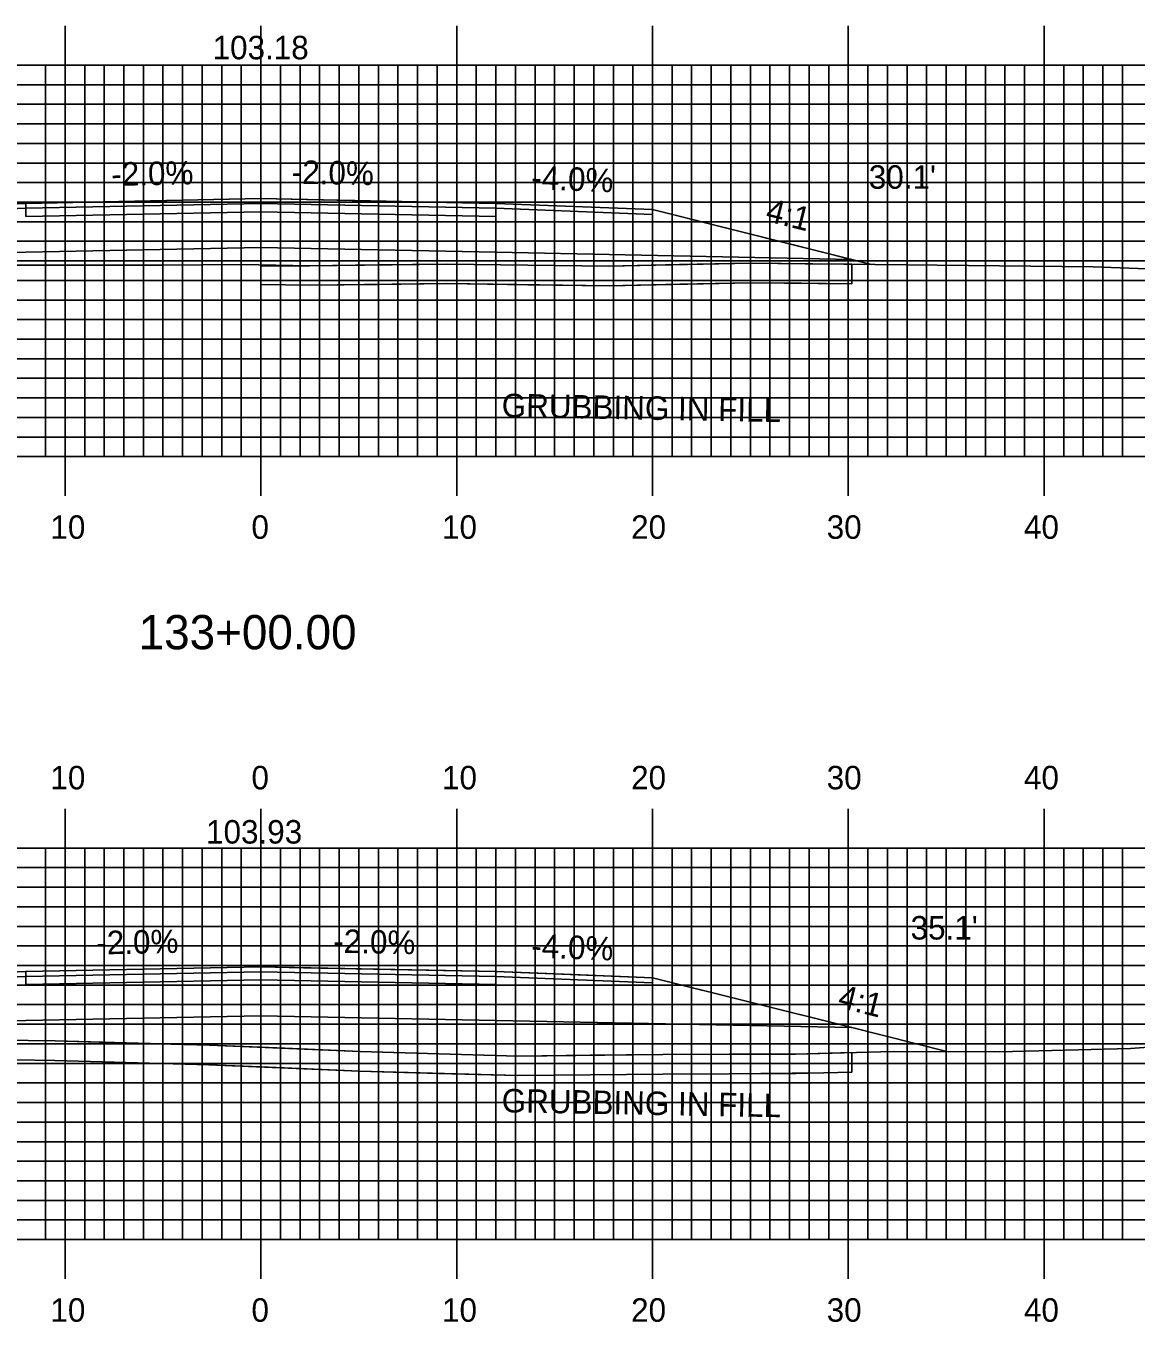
# Model space of a CAD drawing. Extents: x 1774383 to 1774727, y 442591 to 442811.
# Drawn here: x 1774537.2 to 1774593.9, y 442689.4 to 442755.7 of the extents above; entities that cross this region are included whole.
import ezdxf

# ---------------------------------------------------------------- set-up
doc = ezdxf.new("R2010")
doc.units = 0
for name, color, linetype in [('ANNOTATION', 7, 'Continuous'), ('D_Roadway_Centerline', 7, 'Continuous'), ('D_Roadway_Centerline_Text', 7, 'Continuous'), ('D_Roadway_Edge_Shoulder', 7, 'Continuous'), ('D_Roadway_Edge_TW', 7, 'Continuous'), ('D_Roadway_Pavement', 7, 'Continuous'), ('D_Roadway_SlopeLines', 7, 'Continuous'), ('D_Roadway_SubGrade', 7, 'Continuous'), ('D_Text_Standard', 7, 'Continuous'), ('GRUBBING IN FILL', 7, 'Continuous'), ('H_V ANNOTATION', 7, 'Continuous'), ('MAJOR', 7, 'Continuous'), ('MINOR', 7, 'Continuous'), ('S_Roadway_Centerline', 7, 'Continuous')]:
    doc.layers.add(name, color=color, linetype=linetype)

msp = doc.modelspace()

# ---------------------------------------------------------------- linework, layer by layer
at = {"layer": 'D_Roadway_Centerline'}
for points in [[(1774517.069, 442743.258), (1774518.981, 442743.736), (1774518.998, 442743.74), (1774519.832, 442743.949), (1774529.172, 442746.284), (1774537.172, 442746.604), (1774538.705, 442746.635), (1774549.172, 442746.844), (1774556.935, 442746.689), (1774561.172, 442746.604), (1774569.172, 442746.284), (1774579.347, 442743.74), (1774580.365, 442743.486)], [(1774514.75, 442703.428), (1774517.172, 442704.034), (1774518.998, 442704.49), (1774521.759, 442705.181), (1774529.172, 442707.034), (1774537.172, 442707.354), (1774537.174, 442707.354), (1774549.172, 442707.594), (1774551.354, 442707.551), (1774561.173, 442707.354), (1774565.061, 442707.199), (1774569.172, 442707.034), (1774573.892, 442705.854), (1774579.346, 442704.49), (1774584.264, 442703.261)]]:
    msp.add_lwpolyline(points, dxfattribs=at)
at = {"layer": 'D_Roadway_Edge_Shoulder'}
for points in [[(1774537.172, 442746.604), (1774529.172, 442746.284), (1774529.172, 442746.034), (1774537.172, 442746.354)], [(1774561.172, 442746.604), (1774569.172, 442746.284), (1774569.172, 442746.034), (1774561.172, 442746.354)], [(1774537.172, 442707.354), (1774529.172, 442707.034), (1774529.172, 442706.784), (1774537.172, 442707.104)], [(1774561.172, 442707.354), (1774569.172, 442707.034), (1774569.172, 442706.784), (1774561.172, 442707.104)]]:
    msp.add_lwpolyline(points, close=True, dxfattribs=at)
at = {"layer": 'D_Roadway_Edge_TW'}
for points in [[(1774537.172, 442746.354), (1774537.172, 442746.604), (1774549.172, 442746.844), (1774561.172, 442746.604), (1774561.172, 442746.354), (1774549.172, 442746.594)], [(1774537.172, 442707.104), (1774537.172, 442707.354), (1774549.172, 442707.594), (1774561.172, 442707.354), (1774561.172, 442707.104), (1774549.172, 442707.344)]]:
    msp.add_lwpolyline(points, close=True, dxfattribs=at)
at = {"layer": 'D_Roadway_Pavement'}
for points in [[(1774537.172, 442745.937), (1774537.172, 442746.354), (1774549.172, 442746.594), (1774561.172, 442746.354), (1774561.172, 442745.937), (1774549.172, 442746.177)], [(1774537.172, 442706.687), (1774537.172, 442707.104), (1774549.172, 442707.344), (1774561.172, 442707.104), (1774561.172, 442706.687), (1774549.172, 442706.927)]]:
    msp.add_lwpolyline(points, close=True, dxfattribs=at)
at = {"layer": 'D_Roadway_SlopeLines'}
for points in [[(1774569.172, 442746.284), (1774580.365, 442743.485)], [(1774569.172, 442707.034), (1774579.346, 442704.49), (1774584.264, 442703.261)]]:
    msp.add_lwpolyline(points, dxfattribs=at)
at = {"layer": 'D_Roadway_SubGrade'}
for points in [[(1774537.172, 442744.104), (1774518.998, 442743.74), (1774529.172, 442746.284), (1774529.172, 442746.034), (1774537.172, 442746.354), (1774549.172, 442746.594), (1774561.172, 442746.354), (1774569.172, 442746.034), (1774569.172, 442746.284), (1774579.347, 442743.74), (1774561.172, 442744.104), (1774549.172, 442744.344)], [(1774537.172, 442704.854), (1774518.998, 442704.49), (1774529.172, 442707.034), (1774529.172, 442706.784), (1774537.172, 442707.104), (1774549.172, 442707.344), (1774561.172, 442707.104), (1774569.172, 442706.784), (1774569.172, 442707.034), (1774579.346, 442704.49), (1774561.172, 442704.854), (1774549.172, 442705.094)]]:
    msp.add_lwpolyline(points, close=True, dxfattribs=at)
at = {"layer": 'GRUBBING IN FILL'}
for p, q in [((1774549.172, 442742.459), (1774549.172, 442743.416)), ((1774549.172, 442743.416), (1774551.667, 442743.416)), ((1774549.172, 442742.459), (1774549.172, 442743.416)), ((1774549.172, 442743.416), (1774551.667, 442743.416)), ((1774579.347, 442743.496), (1774579.347, 442742.496)), ((1774579.347, 442743.496), (1774579.347, 442742.496)), ((1774579.346, 442703.217), (1774579.346, 442702.216)), ((1774579.346, 442703.217), (1774579.346, 442702.216))]:
    msp.add_line(p, q, dxfattribs=at)
for points in [[(1774549.172, 442742.459), (1774549.172, 442743.416), (1774551.667, 442743.416), (1774555.169, 442743.46), (1774558.671, 442743.503), (1774562.81, 442743.449), (1774566.948, 442743.394), (1774570.557, 442743.473), (1774574.166, 442743.552), (1774576.961, 442743.522), (1774579.347, 442743.496), (1774579.347, 442742.496), (1774576.759, 442742.524), (1774574.172, 442742.552), (1774570.562, 442742.473), (1774566.953, 442742.394), (1774562.812, 442742.449), (1774558.671, 442742.503), (1774555.168, 442742.46), (1774551.665, 442742.416)], [(1774549.172, 442742.459), (1774549.172, 442743.416), (1774551.667, 442743.416), (1774555.169, 442743.46), (1774558.671, 442743.503), (1774562.81, 442743.449), (1774566.948, 442743.394), (1774570.557, 442743.473), (1774574.166, 442743.552), (1774576.961, 442743.522), (1774579.347, 442743.496), (1774579.347, 442742.496), (1774576.759, 442742.524), (1774574.172, 442742.552), (1774570.562, 442742.473), (1774566.953, 442742.394), (1774562.812, 442742.449), (1774558.671, 442742.503), (1774555.168, 442742.46), (1774551.665, 442742.416)], [(1774518.998, 442702.527), (1774525.033, 442702.668), (1774531.069, 442702.808), (1774534.516, 442702.875), (1774538.645, 442702.811), (1774546.521, 442702.599), (1774549.172, 442702.486), (1774549.172, 442703.487), (1774546.555, 442703.599), (1774542.611, 442703.705), (1774538.666, 442703.811), (1774534.514, 442703.875), (1774532.781, 442703.841), (1774531.048, 442703.808), (1774522.901, 442703.618), (1774518.998, 442703.527)], [(1774518.998, 442702.527), (1774525.033, 442702.668), (1774531.069, 442702.808), (1774534.516, 442702.875), (1774538.645, 442702.811), (1774546.521, 442702.599), (1774549.172, 442702.486), (1774549.172, 442703.487), (1774546.555, 442703.599), (1774542.611, 442703.705), (1774538.666, 442703.811), (1774534.514, 442703.875), (1774532.781, 442703.841), (1774531.048, 442703.808), (1774522.901, 442703.618), (1774518.998, 442703.527)], [(1774549.172, 442703.487), (1774550.401, 442703.435), (1774554.247, 442703.271), (1774558.268, 442703.156), (1774562.289, 442703.041), (1774565.991, 442703.08), (1774569.692, 442703.12), (1774573.083, 442703.131), (1774576.475, 442703.142), (1774579.346, 442703.217), (1774579.346, 442702.216), (1774577.918, 442702.179), (1774573.094, 442702.131), (1774569.699, 442702.12), (1774565.989, 442702.08), (1774562.28, 442702.041), (1774558.246, 442702.156), (1774554.212, 442702.272), (1774550.366, 442702.436), (1774549.172, 442702.486)], [(1774549.172, 442703.487), (1774550.401, 442703.435), (1774554.247, 442703.271), (1774558.268, 442703.156), (1774562.289, 442703.041), (1774565.991, 442703.08), (1774569.692, 442703.12), (1774573.083, 442703.131), (1774576.475, 442703.142), (1774579.346, 442703.217), (1774579.346, 442702.216), (1774577.918, 442702.179), (1774573.094, 442702.131), (1774569.699, 442702.12), (1774565.989, 442702.08), (1774562.28, 442702.041), (1774558.246, 442702.156), (1774554.212, 442702.272), (1774550.366, 442702.436), (1774549.172, 442702.486)]]:
    msp.add_lwpolyline(points, close=True, dxfattribs=at)
for points in [[(1774549.172, 442742.459), (1774551.665, 442742.416), (1774558.671, 442742.503), (1774566.953, 442742.394), (1774574.172, 442742.552), (1774579.347, 442742.496)], [(1774549.172, 442742.459), (1774551.665, 442742.416), (1774558.671, 442742.503), (1774566.953, 442742.394), (1774574.172, 442742.552), (1774579.347, 442742.496)], [(1774518.998, 442702.527), (1774531.069, 442702.808), (1774534.516, 442702.875), (1774538.645, 442702.811), (1774546.521, 442702.599), (1774554.212, 442702.272), (1774562.28, 442702.041), (1774569.699, 442702.12), (1774576.489, 442702.142), (1774579.346, 442702.216)], [(1774518.998, 442702.527), (1774531.069, 442702.808), (1774534.516, 442702.875), (1774538.645, 442702.811), (1774546.521, 442702.599), (1774554.212, 442702.272), (1774562.28, 442702.041), (1774569.699, 442702.12), (1774576.489, 442702.142), (1774579.346, 442702.216)]]:
    msp.add_lwpolyline(points, dxfattribs=at)
at = {"layer": 'MAJOR'}
for p, q in [((1774539.172, 442755.669), (1774539.172, 442753.665)), ((1774549.172, 442755.669), (1774549.172, 442753.665)), ((1774559.172, 442755.669), (1774559.172, 442753.665)), ((1774569.172, 442755.669), (1774569.172, 442753.665)), ((1774579.172, 442755.669), (1774579.172, 442753.665)), ((1774589.172, 442755.669), (1774589.172, 442753.665)), ((1774409.172, 442753.665), (1774689.172, 442753.665)), ((1774409.172, 442753.665), (1774689.172, 442753.665)), ((1774539.172, 442733.665), (1774539.172, 442753.665)), ((1774549.172, 442733.665), (1774549.172, 442753.665)), ((1774559.172, 442733.665), (1774559.172, 442753.665)), ((1774569.172, 442733.665), (1774569.172, 442753.665)), ((1774579.172, 442733.665), (1774579.172, 442753.665)), ((1774589.172, 442733.665), (1774589.172, 442753.665)), ((1774409.172, 442748.665), (1774689.172, 442748.665)), ((1774409.172, 442743.665), (1774689.172, 442743.665)), ((1774409.172, 442738.665), (1774689.172, 442738.665)), ((1774409.172, 442733.665), (1774689.172, 442733.665)), ((1774409.172, 442733.665), (1774689.172, 442733.665)), ((1774539.172, 442731.661), (1774539.172, 442733.665)), ((1774549.172, 442731.661), (1774549.172, 442733.665)), ((1774559.172, 442731.661), (1774559.172, 442733.665)), ((1774569.172, 442731.661), (1774569.172, 442733.665)), ((1774579.172, 442731.661), (1774579.172, 442733.665)), ((1774589.172, 442731.661), (1774589.172, 442733.665)), ((1774539.172, 442715.669), (1774539.172, 442713.665)), ((1774549.172, 442715.669), (1774549.172, 442713.665)), ((1774559.172, 442715.669), (1774559.172, 442713.665)), ((1774569.172, 442715.669), (1774569.172, 442713.665)), ((1774579.172, 442715.669), (1774579.172, 442713.665)), ((1774589.172, 442715.669), (1774589.172, 442713.665)), ((1774409.172, 442713.665), (1774689.172, 442713.665)), ((1774409.172, 442713.665), (1774689.172, 442713.665)), ((1774539.172, 442693.665), (1774539.172, 442713.665)), ((1774549.172, 442693.665), (1774549.172, 442713.665)), ((1774559.172, 442693.665), (1774559.172, 442713.665)), ((1774569.172, 442693.665), (1774569.172, 442713.665)), ((1774579.172, 442693.665), (1774579.172, 442713.665)), ((1774589.172, 442693.665), (1774589.172, 442713.665)), ((1774409.172, 442708.665), (1774689.172, 442708.665)), ((1774409.172, 442703.665), (1774689.172, 442703.665)), ((1774409.172, 442698.665), (1774689.172, 442698.665)), ((1774409.172, 442693.665), (1774689.172, 442693.665)), ((1774409.172, 442693.665), (1774689.172, 442693.665)), ((1774539.172, 442691.661), (1774539.172, 442693.665)), ((1774549.172, 442691.661), (1774549.172, 442693.665)), ((1774559.172, 442691.661), (1774559.172, 442693.665)), ((1774569.172, 442691.661), (1774569.172, 442693.665)), ((1774579.172, 442691.661), (1774579.172, 442693.665)), ((1774589.172, 442691.661), (1774589.172, 442693.665))]:
    msp.add_line(p, q, dxfattribs=at)
at = {"layer": 'MINOR'}
for p, q in [((1774538.172, 442733.665), (1774538.172, 442753.665)), ((1774540.172, 442733.665), (1774540.172, 442753.665)), ((1774541.172, 442733.665), (1774541.172, 442753.665)), ((1774542.172, 442733.665), (1774542.172, 442753.665)), ((1774543.172, 442733.665), (1774543.172, 442753.665)), ((1774544.172, 442733.665), (1774544.172, 442753.665)), ((1774545.172, 442733.665), (1774545.172, 442753.665)), ((1774546.172, 442733.665), (1774546.172, 442753.665)), ((1774547.172, 442733.665), (1774547.172, 442753.665)), ((1774548.172, 442733.665), (1774548.172, 442753.665)), ((1774550.172, 442733.665), (1774550.172, 442753.665)), ((1774551.172, 442733.665), (1774551.172, 442753.665)), ((1774552.172, 442733.665), (1774552.172, 442753.665)), ((1774553.172, 442733.665), (1774553.172, 442753.665)), ((1774554.172, 442733.665), (1774554.172, 442753.665)), ((1774555.172, 442733.665), (1774555.172, 442753.665)), ((1774556.172, 442733.665), (1774556.172, 442753.665)), ((1774557.172, 442733.665), (1774557.172, 442753.665)), ((1774558.172, 442733.665), (1774558.172, 442753.665)), ((1774560.172, 442733.665), (1774560.172, 442753.665)), ((1774561.172, 442733.665), (1774561.172, 442753.665)), ((1774562.172, 442733.665), (1774562.172, 442753.665)), ((1774563.172, 442733.665), (1774563.172, 442753.665)), ((1774564.172, 442733.665), (1774564.172, 442753.665)), ((1774565.172, 442733.665), (1774565.172, 442753.665)), ((1774566.172, 442733.665), (1774566.172, 442753.665)), ((1774567.172, 442733.665), (1774567.172, 442753.665)), ((1774568.172, 442733.665), (1774568.172, 442753.665)), ((1774570.172, 442733.665), (1774570.172, 442753.665)), ((1774571.172, 442733.665), (1774571.172, 442753.665)), ((1774572.172, 442733.665), (1774572.172, 442753.665)), ((1774573.172, 442733.665), (1774573.172, 442753.665)), ((1774574.172, 442733.665), (1774574.172, 442753.665)), ((1774575.172, 442733.665), (1774575.172, 442753.665)), ((1774576.172, 442733.665), (1774576.172, 442753.665)), ((1774577.172, 442733.665), (1774577.172, 442753.665)), ((1774578.172, 442733.665), (1774578.172, 442753.665)), ((1774580.172, 442733.665), (1774580.172, 442753.665)), ((1774581.172, 442733.665), (1774581.172, 442753.665)), ((1774582.172, 442733.665), (1774582.172, 442753.665)), ((1774583.172, 442733.665), (1774583.172, 442753.665)), ((1774584.172, 442733.665), (1774584.172, 442753.665)), ((1774585.172, 442733.665), (1774585.172, 442753.665)), ((1774586.172, 442733.665), (1774586.172, 442753.665)), ((1774587.172, 442733.665), (1774587.172, 442753.665)), ((1774588.172, 442733.665), (1774588.172, 442753.665)), ((1774590.172, 442733.665), (1774590.172, 442753.665)), ((1774591.172, 442733.665), (1774591.172, 442753.665)), ((1774592.172, 442733.665), (1774592.172, 442753.665)), ((1774593.172, 442733.665), (1774593.172, 442753.665)), ((1774409.172, 442752.665), (1774689.172, 442752.665)), ((1774409.172, 442751.665), (1774689.172, 442751.665)), ((1774409.172, 442750.665), (1774689.172, 442750.665)), ((1774409.172, 442749.665), (1774689.172, 442749.665)), ((1774409.172, 442747.665), (1774689.172, 442747.665)), ((1774409.172, 442746.665), (1774689.172, 442746.665)), ((1774409.172, 442745.665), (1774689.172, 442745.665)), ((1774409.172, 442744.665), (1774689.172, 442744.665)), ((1774409.172, 442742.665), (1774689.172, 442742.665)), ((1774409.172, 442741.665), (1774689.172, 442741.665)), ((1774409.172, 442740.665), (1774689.172, 442740.665)), ((1774409.172, 442739.665), (1774689.172, 442739.665)), ((1774409.172, 442737.665), (1774689.172, 442737.665)), ((1774409.172, 442736.665), (1774689.172, 442736.665)), ((1774409.172, 442735.665), (1774689.172, 442735.665)), ((1774409.172, 442734.665), (1774689.172, 442734.665)), ((1774538.172, 442693.665), (1774538.172, 442713.665)), ((1774540.172, 442693.665), (1774540.172, 442713.665)), ((1774541.172, 442693.665), (1774541.172, 442713.665)), ((1774542.172, 442693.665), (1774542.172, 442713.665)), ((1774543.172, 442693.665), (1774543.172, 442713.665)), ((1774544.172, 442693.665), (1774544.172, 442713.665)), ((1774545.172, 442693.665), (1774545.172, 442713.665)), ((1774546.172, 442693.665), (1774546.172, 442713.665)), ((1774547.172, 442693.665), (1774547.172, 442713.665)), ((1774548.172, 442693.665), (1774548.172, 442713.665)), ((1774550.172, 442693.665), (1774550.172, 442713.665)), ((1774551.172, 442693.665), (1774551.172, 442713.665)), ((1774552.172, 442693.665), (1774552.172, 442713.665)), ((1774553.172, 442693.665), (1774553.172, 442713.665)), ((1774554.172, 442693.665), (1774554.172, 442713.665)), ((1774555.172, 442693.665), (1774555.172, 442713.665)), ((1774556.172, 442693.665), (1774556.172, 442713.665)), ((1774557.172, 442693.665), (1774557.172, 442713.665)), ((1774558.172, 442693.665), (1774558.172, 442713.665)), ((1774560.172, 442693.665), (1774560.172, 442713.665)), ((1774561.172, 442693.665), (1774561.172, 442713.665)), ((1774562.172, 442693.665), (1774562.172, 442713.665)), ((1774563.172, 442693.665), (1774563.172, 442713.665)), ((1774564.172, 442693.665), (1774564.172, 442713.665)), ((1774565.172, 442693.665), (1774565.172, 442713.665)), ((1774566.172, 442693.665), (1774566.172, 442713.665)), ((1774567.172, 442693.665), (1774567.172, 442713.665)), ((1774568.172, 442693.665), (1774568.172, 442713.665)), ((1774570.172, 442693.665), (1774570.172, 442713.665)), ((1774571.172, 442693.665), (1774571.172, 442713.665)), ((1774572.172, 442693.665), (1774572.172, 442713.665)), ((1774573.172, 442693.665), (1774573.172, 442713.665)), ((1774574.172, 442693.665), (1774574.172, 442713.665)), ((1774575.172, 442693.665), (1774575.172, 442713.665)), ((1774576.172, 442693.665), (1774576.172, 442713.665)), ((1774577.172, 442693.665), (1774577.172, 442713.665)), ((1774578.172, 442693.665), (1774578.172, 442713.665)), ((1774580.172, 442693.665), (1774580.172, 442713.665)), ((1774581.172, 442693.665), (1774581.172, 442713.665)), ((1774582.172, 442693.665), (1774582.172, 442713.665)), ((1774583.172, 442693.665), (1774583.172, 442713.665)), ((1774584.172, 442693.665), (1774584.172, 442713.665)), ((1774585.172, 442693.665), (1774585.172, 442713.665)), ((1774586.172, 442693.665), (1774586.172, 442713.665)), ((1774587.172, 442693.665), (1774587.172, 442713.665)), ((1774588.172, 442693.665), (1774588.172, 442713.665)), ((1774590.172, 442693.665), (1774590.172, 442713.665)), ((1774591.172, 442693.665), (1774591.172, 442713.665)), ((1774592.172, 442693.665), (1774592.172, 442713.665)), ((1774593.172, 442693.665), (1774593.172, 442713.665)), ((1774409.172, 442712.665), (1774689.172, 442712.665)), ((1774409.172, 442711.665), (1774689.172, 442711.665)), ((1774409.172, 442710.665), (1774689.172, 442710.665)), ((1774409.172, 442709.665), (1774689.172, 442709.665)), ((1774409.172, 442707.665), (1774689.172, 442707.665)), ((1774409.172, 442706.665), (1774689.172, 442706.665)), ((1774409.172, 442705.665), (1774689.172, 442705.665)), ((1774409.172, 442704.665), (1774689.172, 442704.665)), ((1774409.172, 442702.665), (1774689.172, 442702.665)), ((1774409.172, 442701.665), (1774689.172, 442701.665)), ((1774409.172, 442700.665), (1774689.172, 442700.665)), ((1774409.172, 442699.665), (1774689.172, 442699.665)), ((1774409.172, 442697.665), (1774689.172, 442697.665)), ((1774409.172, 442696.665), (1774689.172, 442696.665)), ((1774409.172, 442695.665), (1774689.172, 442695.665)), ((1774409.172, 442694.665), (1774689.172, 442694.665))]:
    msp.add_line(p, q, dxfattribs=at)
at = {"layer": 'S_Roadway_Centerline'}
for points in [[(1774476.385, 442742.731), (1774488.815, 442743.149), (1774495.737, 442742.975), (1774501.567, 442743.041), (1774505.644, 442743.206), (1774512.039, 442743.175), (1774519.175, 442743.293), (1774523.952, 442743.363), (1774528.363, 442743.241), (1774535.941, 442743.448), (1774544.165, 442743.454), (1774548.194, 442743.476), (1774551.667, 442743.416), (1774558.671, 442743.503), (1774566.948, 442743.394), (1774574.166, 442743.552), (1774591.672, 442743.364), (1774594.434, 442743.266)], [(1774485.788, 442703.221), (1774491.276, 442703.231), (1774508.898, 442703.401), (1774511.723, 442703.371), (1774514.755, 442703.428), (1774531.048, 442703.808), (1774534.514, 442703.875), (1774538.666, 442703.811), (1774546.555, 442703.599), (1774554.247, 442703.271), (1774562.289, 442703.041), (1774569.692, 442703.12), (1774576.475, 442703.142), (1774581.467, 442703.272), (1774586.892, 442703.25), (1774593.584, 442703.419), (1774600.43, 442703.939)]]:
    msp.add_lwpolyline(points, dxfattribs=at)

# ---------------------------------------------------------------- texts
at = {"layer": 'ANNOTATION'}
for s, rotation, p in [('-2.0%', 1.14582, (1774541.544, 442747.492)), ('-2.0%', 358.85424, (1774550.739, 442747.613)), ('-4.0%', 357.70947, (1774562.964, 442747.334)), ('4:1', 345.96159, (1774574.893, 442745.715)), ('-2.0%', 1.14579, (1774540.779, 442708.227)), ('-2.0%', 358.85424, (1774552.859, 442708.321)), ('-4.0%', 357.70926, (1774562.964, 442708.084)), ('4:1', 345.96467, (1774578.584, 442705.543))]:
    msp.add_text(s, height=1.2, rotation=rotation, dxfattribs=at).set_placement(p)
at = {"layer": 'D_Roadway_Centerline'}
for s, p in [('C', (1774549.166, 442746.844)), ('L', (1774549.172, 442746.837)), ('C', (1774549.167, 442707.594)), ('L', (1774549.172, 442707.587))]:
    msp.add_text(s, height=0.0146, dxfattribs=at).set_placement(p)
at = {"layer": 'D_Roadway_Centerline_Text'}
for s, p in [('103.18', (1774546.706, 442753.963)), ('103.93', (1774546.374, 442713.895))]:
    msp.add_text(s, height=1.2, dxfattribs=at).set_placement(p)
at = {"layer": 'D_Text_Standard'}
for s, p in [("30.1'", (1774580.22, 442747.349)), ("35.1'", (1774582.355, 442708.992))]:
    msp.add_text(s, height=1.2, dxfattribs=at).set_placement(p)
at = {"layer": 'GRUBBING IN FILL'}
for p in [(1774561.463, 442735.685), (1774561.463, 442700.168)]:
    msp.add_text('GRUBBING IN FILL', height=1.2, rotation=358.9728, dxfattribs=at).set_placement(p)
at = {"layer": 'H_V ANNOTATION'}
for s, height, p in [('10', 1.2, (1774538.423, 442729.465)), ('0', 1.2, (1774548.69, 442729.465)), ('10', 1.2, (1774558.423, 442729.465)), ('20', 1.2, (1774568.08, 442729.465)), ('30', 1.2, (1774578.069, 442729.465)), ('40', 1.2, (1774588.144, 442729.465)), ('133+00.00', 1.75, (1774542.93, 442723.821)), ('10', 1.2, (1774538.423, 442716.665)), ('0', 1.2, (1774548.69, 442716.665)), ('10', 1.2, (1774558.423, 442716.665)), ('20', 1.2, (1774568.08, 442716.665)), ('30', 1.2, (1774578.069, 442716.665)), ('40', 1.2, (1774588.144, 442716.665)), ('10', 1.2, (1774538.423, 442689.465)), ('0', 1.2, (1774548.69, 442689.465)), ('10', 1.2, (1774558.423, 442689.465)), ('20', 1.2, (1774568.08, 442689.465)), ('30', 1.2, (1774578.069, 442689.465)), ('40', 1.2, (1774588.144, 442689.465))]:
    msp.add_text(s, height=height, dxfattribs=at).set_placement(p)

doc.saveas('drawing.dxf')
